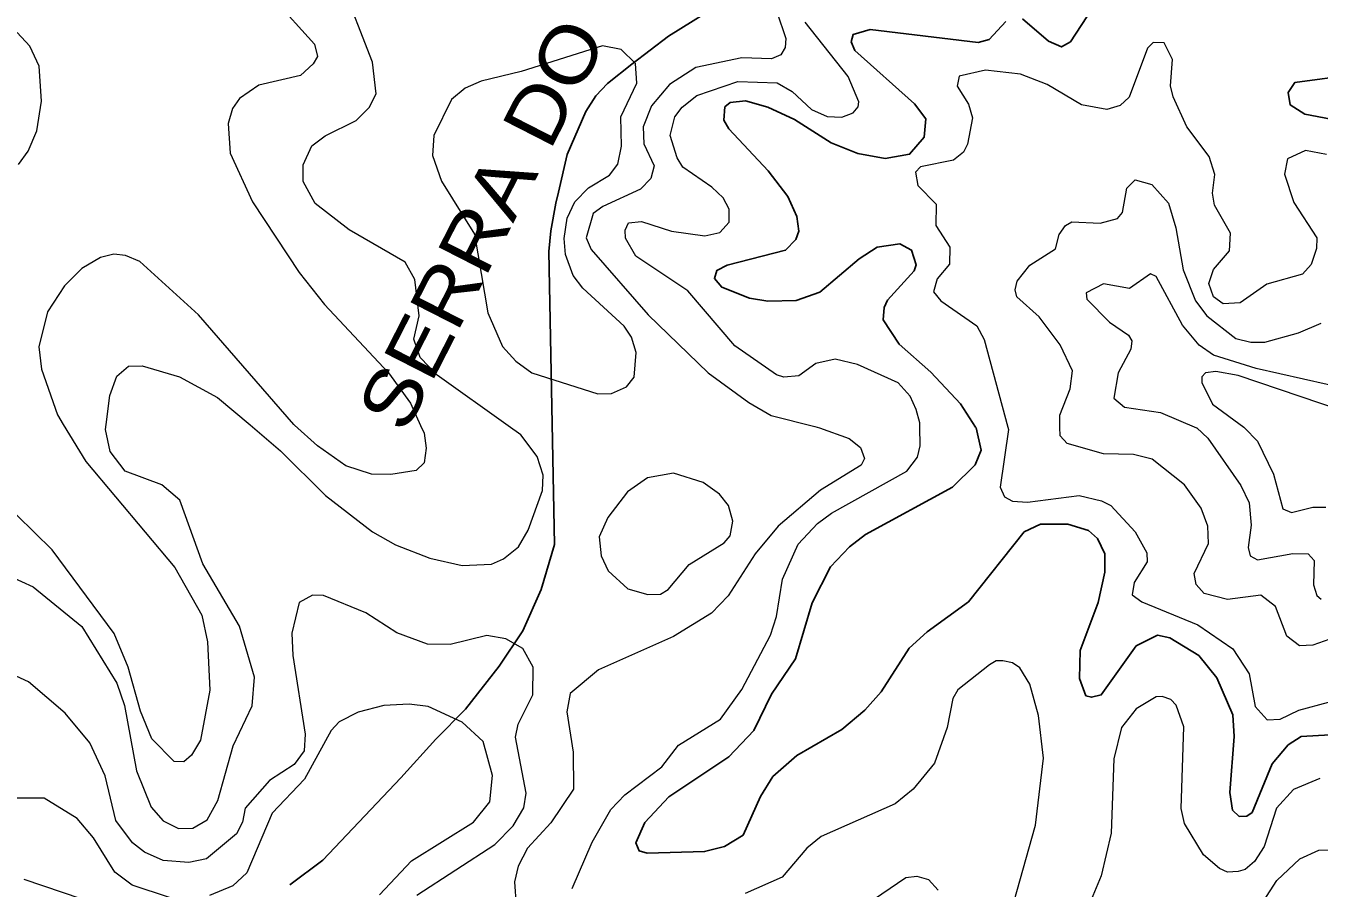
# Model space of a CAD drawing. Extents: x 473.9 to 500, y 7733.1 to 7760.8.
# Drawn here: x 484.875 to 487.667, y 7745.353 to 7747.215 of the extents above; entities that cross this region are included whole.
import ezdxf
from ezdxf.enums import TextEntityAlignment as Align

# ---------------------------------------------------------------- set-up
doc = ezdxf.new("R2010")
doc.units = 0
doc.header["$LTSCALE"] = 0.032
for name, color, linetype, lineweight in [('1', 7, 'Continuous', 25), ('2', 7, 'Continuous', 13), ('26', 7, 'Continuous', 25)]:
    doc.layers.add(name, color=color, linetype=linetype, lineweight=lineweight)

msp = doc.modelspace()

# ---------------------------------------------------------------- linework, layer by layer
at = {"layer": '1'}
for points in [[(487.1661, 7747.234), (487.1303, 7747.1799), (487.1109, 7747.1691), (487.0831, 7747.1814), (487.0268, 7747.2295)], [(486.991, 7747.2242), (486.9546, 7747.1848), (486.9312, 7747.179), (486.6977, 7747.2069), (486.661, 7747.1958), (486.657, 7747.1798), (486.6648, 7747.1611), (486.7936, 7747.0462), (486.8182, 7747.014), (486.8145, 7746.9742), (486.7831, 7746.9375), (486.7301, 7746.9282), (486.6714, 7746.9387), (486.6138, 7746.9622), (486.5345, 7747.0122), (486.4767, 7747.0388), (486.4287, 7747.0528)], [(487.8745, 7746.9789), (487.6368, 7747.0239), (487.6051, 7747.0438), (487.6004, 7747.0708), (487.6149, 7747.092), (487.7438, 7747.1092)], [(486.4287, 7747.0528), (486.3952, 7747.0489), (486.3838, 7747.0395), (486.3817, 7747.0111), (486.3925, 7746.9924), (486.4773, 7746.9014), (486.5202, 7746.8461), (486.5395, 7746.8026), (486.5436, 7746.7712), (486.5371, 7746.7534), (486.5152, 7746.7302), (486.3889, 7746.6978), (486.3668, 7746.6866), (486.3615, 7746.6689), (486.3773, 7746.6506), (486.437, 7746.6268), (486.4768, 7746.6205), (486.5379, 7746.6217), (486.5895, 7746.6395), (486.6744, 7746.7119), (486.7133, 7746.7366), (486.7618, 7746.7439), (486.7871, 7746.7305), (486.7974, 7746.6988), (486.7931, 7746.6857), (486.7353, 7746.6222), (486.7279, 7746.6067), (486.726, 7746.5795), (486.7605, 7746.5273), (486.8287, 7746.467), (486.893, 7746.3987), (486.9256, 7746.3483), (486.9268, 7746.3464), (486.9375, 7746.2981), (486.9248, 7746.2668), (486.876, 7746.2186), (486.6878, 7746.1165), (486.6535, 7746.0899), (486.6124, 7746.0465), (486.5725, 7745.9685), (486.5363, 7745.8476), (486.4848, 7745.7715), (486.4467, 7745.6934), (486.3929, 7745.6364), (486.2634, 7745.5496), (486.2111, 7745.4942), (486.1915, 7745.4508), (486.1993, 7745.433), (486.2161, 7745.428), (486.3404, 7745.4318), (486.3831, 7745.4428), (486.4236, 7745.4674), (486.4611, 7745.5506), (486.4875, 7745.5937), (486.5397, 7745.6392), (486.6364, 7745.6954), (486.6863, 7745.7369), (486.7216, 7745.7765), (486.7824, 7745.8706), (486.8208, 7745.9061), (486.9102, 7745.9706), (487.0306, 7746.1221), (487.0657, 7746.1383), (487.1248, 7746.1384), (487.1691, 7746.1247), (487.1888, 7746.1076), (487.2045, 7746.0747), (487.2047, 7746.0353), (487.19, 7745.9698), (487.1516, 7745.8658), (487.15, 7745.8051), (487.1637, 7745.7681), (487.1761, 7745.7648), (487.197, 7745.7698), (487.2724, 7745.8759), (487.3183, 7745.8988), (487.345, 7745.8931), (487.4074, 7745.8551), (487.4468, 7745.8068), (487.481, 7745.7269), (487.4843, 7745.6803), (487.4747, 7745.559), (487.4806, 7745.5213), (487.4947, 7745.5078), (487.511, 7745.5083), (487.5228, 7745.5164), (487.5659, 7745.6213), (487.6008, 7745.6625), (487.6287, 7745.6801), (487.6915, 7745.6838)]]:
    msp.add_lwpolyline(points, dxfattribs=at)
at = {"layer": '2'}
for points in [[(484.8139, 7746.0378), (484.89, 7746.0036), (484.9957, 7745.918), (485.0712, 7745.795), (485.0873, 7745.7468), (485.1133, 7745.6063), (485.1448, 7745.5277), (485.171, 7745.4981), (485.2042, 7745.4813), (485.235, 7745.4826), (485.2659, 7745.5002), (485.289, 7745.5419), (485.3221, 7745.6599), (485.3633, 7745.7463), (485.3682, 7745.8086), (485.3358, 7745.9183), (485.2567, 7746.0529), (485.207, 7746.1905), (485.1682, 7746.2239), (485.0889, 7746.2532), (485.0568, 7746.2956), (485.0465, 7746.3433), (485.0478, 7746.354), (485.0556, 7746.4162), (485.0708, 7746.4584), (485.0965, 7746.4795), (485.1259, 7746.4808), (485.2063, 7746.4567), (485.2882, 7746.4124), (485.3587, 7746.353), (485.4248, 7746.2973), (485.5217, 7746.2004), (485.6234, 7746.122), (485.6731, 7746.0939), (485.7471, 7746.0651), (485.8166, 7746.0493), (485.88, 7746.0521), (485.9059, 7746.0635), (485.9386, 7746.0899), (485.959, 7746.1257), (485.99, 7746.211), (485.992, 7746.2442), (485.9784, 7746.2849), (485.9438, 7746.3316), (485.9159, 7746.3513), (485.7625, 7746.4601), (485.726, 7746.4987), (485.7123, 7746.5379), (485.7237, 7746.5888), (485.7148, 7746.6671), (485.6934, 7746.7047), (485.5728, 7746.7742), (485.4993, 7746.8309), (485.4735, 7746.8782), (485.4737, 7746.9146), (485.492, 7746.9554), (485.5207, 7746.9772), (485.5877, 7747.0104), (485.6157, 7747.0384), (485.631, 7747.0675), (485.6228, 7747.136), (485.555, 7747.3123)], [(485.4092, 7747.2739), (485.4977, 7747.175), (485.5041, 7747.1485), (485.4952, 7747.1324), (485.4679, 7747.1075), (485.3779, 7747.0866), (485.336, 7747.0576), (485.3208, 7747.0359), (485.3111, 7747.0038), (485.3159, 7746.9394), (485.3642, 7746.8349), (485.4647, 7746.6821), (485.5194, 7746.613), (485.6577, 7746.4651), (485.7051, 7746.3999), (485.727, 7746.3519), (485.7348, 7746.3348), (485.7389, 7746.3027), (485.7348, 7746.2713), (485.7172, 7746.2544), (485.6625, 7746.2456), (485.6207, 7746.2464), (485.5652, 7746.2649), (485.5041, 7746.3075), (485.4549, 7746.3527), (485.4534, 7746.3541), (485.2476, 7746.5905), (485.1206, 7746.7055), (485.09, 7746.7191), (485.0643, 7746.7215), (485.0354, 7746.7143), (484.9952, 7746.691), (484.9582, 7746.6532), (484.9212, 7746.5969), (484.9027, 7746.5213), (484.9083, 7746.4731), (484.9429, 7746.375), (484.9554, 7746.3542), (485.004, 7746.2737), (485.1961, 7746.0454), (485.2548, 7745.9425), (485.2669, 7745.8846), (485.2717, 7745.78), (485.2516, 7745.6723), (485.2323, 7745.6401), (485.2154, 7745.6257), (485.1945, 7745.6265), (485.1463, 7745.6755), (485.1222, 7745.735), (485.0956, 7745.8299), (485.0651, 7745.9023), (484.9316, 7746.0832), (484.8552, 7746.1579)], [(486.4964, 7747.2445), (486.5154, 7747.187), (486.5145, 7747.1679), (486.5049, 7747.1519), (486.4847, 7747.1434), (486.4209, 7747.1452), (486.3212, 7747.1247), (486.2643, 7747.0876), (486.2259, 7747.0422), (486.2078, 7746.9967), (486.2094, 7746.9597), (486.2316, 7746.912), (486.2245, 7746.8853), (486.202, 7746.8619), (486.1203, 7746.8248), (486.0996, 7746.8095), (486.0846, 7746.7568), (486.0957, 7746.7315), (486.2183, 7746.5908), (486.3479, 7746.4654), (486.4356, 7746.4011), (486.4841, 7746.3734), (486.5785, 7746.3493), (486.5881, 7746.3469), (486.6524, 7746.3236), (486.6771, 7746.3041), (486.6859, 7746.2803), (486.6781, 7746.2659), (486.5903, 7746.2117), (486.4995, 7746.1346), (486.4497, 7746.0747), (486.3912, 7745.9838), (486.355, 7745.9466)], [(484.8585, 7746.9153), (484.8794, 7746.9443), (484.8979, 7746.9877), (484.9083, 7747.052), (484.9035, 7747.1276), (484.8834, 7747.171), (484.856, 7747.1999)], [(486.3234, 7747.064), (486.4118, 7747.0946), (486.4971, 7747.0914), (486.5292, 7747.0729), (486.571, 7747.0343), (486.6048, 7747.019), (486.637, 7747.0174), (486.6611, 7747.0271), (486.6723, 7747.0399), (486.6731, 7747.0504), (486.6506, 7747.1051), (486.5573, 7747.2224)], [(487.6837, 7746.9369), (487.6378, 7746.9456), (487.5991, 7746.9272), (487.5928, 7746.8946), (487.613, 7746.833), (487.6625, 7746.7569), (487.6619, 7746.7336), (487.6504, 7746.6993), (487.6318, 7746.6787), (487.5548, 7746.6566), (487.4967, 7746.6167), (487.4604, 7746.6145), (487.4391, 7746.6292), (487.4289, 7746.6586), (487.4393, 7746.6882), (487.4738, 7746.7287), (487.4761, 7746.7673), (487.4413, 7746.8273), (487.4369, 7746.8536), (487.4425, 7746.8938), (487.4297, 7746.9324), (487.3817, 7746.9962), (487.3519, 7747.061), (487.3468, 7747.0851), (487.3509, 7747.1416), (487.3328, 7747.1776), (487.3089, 7747.1785), (487.2966, 7747.1666), (487.2572, 7747.0605), (487.2377, 7747.0429), (487.2088, 7747.0342), (487.1546, 7747.0437), (487.0802, 7747.0876), (487.0223, 7747.1104), (486.9467, 7747.1186), (486.8903, 7747.1056), (486.8855, 7747.0842), (486.9102, 7747.0455), (486.9192, 7747.016), (486.9083, 7746.9589), (486.8993, 7746.9422), (486.8777, 7746.9246), (486.8067, 7746.9099), (486.7961, 7746.8987), (486.801, 7746.87), (486.8403, 7746.8299), (486.8394, 7746.7838), (486.8699, 7746.7365), (486.869, 7746.7001), (486.8425, 7746.6687), (486.8345, 7746.6406), (486.8508, 7746.6211), (486.9279, 7746.5668), (486.944, 7746.5373), (486.9955, 7746.3481), (486.9969, 7746.3429), (486.9789, 7746.2186), (486.9883, 7746.1975), (487.0053, 7746.1883), (487.0373, 7746.1861), (487.1493, 7746.2004), (487.1976, 7746.1893), (487.2175, 7746.1787), (487.27, 7746.122), (487.2956, 7746.0765), (487.296, 7746.057), (487.2678, 7746.0125), (487.2639, 7745.9862), (487.2844, 7745.9708), (487.4053, 7745.9211)], [(486.054, 7745.3523), (486.0974, 7745.452), (486.1376, 7745.5228), (486.1682, 7745.5541), (486.2478, 7745.6144), (486.284, 7745.6618), (486.3748, 7745.7173), (486.4207, 7745.7816), (486.4826, 7745.899), (486.4954, 7745.9392), (486.5083, 7746.0196), (486.5421, 7746.0952), (486.5839, 7746.1402), (486.6144, 7746.1627), (486.7769, 7746.2528), (486.8002, 7746.2834), (486.8058, 7746.3075), (486.8051, 7746.3487), (486.805, 7746.3573), (486.7969, 7746.3863), (486.7841, 7746.4152), (486.7583, 7746.4441), (486.6707, 7746.4835), (486.6225, 7746.4948), (486.5807, 7746.4852), (486.5437, 7746.4586), (486.5115, 7746.4562), (486.4954, 7746.461), (486.4054, 7746.5237), (486.3041, 7746.6427), (486.1915, 7746.7175), (486.1698, 7746.7561), (486.169, 7746.7738), (486.1762, 7746.7891), (486.2044, 7746.7923), (486.2687, 7746.7714), (486.3411, 7746.7609), (486.3732, 7746.7682), (486.3933, 7746.7907), (486.3933, 7746.8188), (486.3805, 7746.8429), (486.3563, 7746.8663), (486.2936, 7746.9097), (486.2808, 7746.9298), (486.2663, 7746.978), (486.2759, 7747.0182), (486.292, 7747.0391), (486.3234, 7747.064)], [(487.703, 7745.8949), (487.6542, 7745.8772), (487.6253, 7745.876), (487.5977, 7745.8971), (487.5732, 7745.9609), (487.5416, 7745.9854), (487.4699, 7745.9762), (487.4193, 7745.9891), (487.4018, 7746.0081), (487.3975, 7746.0319), (487.4284, 7746.0968), (487.4271, 7746.1343), (487.413, 7746.1734), (487.3769, 7746.2233), (487.3069, 7746.2788), (487.2667, 7746.289), (487.2019, 7746.2906), (487.1236, 7746.3127), (487.1079, 7746.3297), (487.1077, 7746.3478), (487.1073, 7746.3739), (487.13, 7746.4307), (487.1345, 7746.4697), (487.1082, 7746.5255), (487.0626, 7746.5861), (487.0147, 7746.6295), (487.0108, 7746.6447), (487.0154, 7746.6635), (487.0429, 7746.6977), (487.0983, 7746.733), (487.1059, 7746.7644), (487.1198, 7746.7838), (487.1333, 7746.7914), (487.1945, 7746.7886), (487.2317, 7746.7987), (487.243, 7746.8117), (487.252, 7746.8638), (487.2705, 7746.882), (487.3058, 7746.872), (487.3419, 7746.8317), (487.3582, 7746.7787), (487.3735, 7746.688), (487.4003, 7746.6209), (487.425, 7746.5886), (487.4877, 7746.5398), (487.52, 7746.5314), (487.55, 7746.5314), (487.6227, 7746.5517), (487.6717, 7746.5729)], [(487.7356, 7746.429), (487.5315, 7746.4749), (487.4394, 7746.5037), (487.4083, 7746.525), (487.3723, 7746.5684), (487.3152, 7746.6737), (487.3031, 7746.6789), (487.2582, 7746.6476), (487.2015, 7746.6579), (487.1645, 7746.6382), (487.166, 7746.6247), (487.2147, 7746.5751), (487.2561, 7746.547), (487.2627, 7746.5346), (487.2611, 7746.5162), (487.2336, 7746.4656), (487.2239, 7746.4108), (487.2474, 7746.3916), (487.3246, 7746.3795), (487.4029, 7746.347), (487.4031, 7746.3469), (487.4272, 7746.3245), (487.4985, 7746.2223), (487.5165, 7746.1847), (487.5205, 7746.1364), (487.5141, 7746.0882), (487.5187, 7746.0701), (487.5343, 7746.0618), (487.6103, 7746.0751), (487.6437, 7746.0749), (487.6568, 7746.0605), (487.6556, 7746.0078), (487.6627, 7745.9845), (487.6719, 7745.9769)], [(487.7604, 7746.3689), (487.4923, 7746.4593), (487.4441, 7746.4682), (487.4219, 7746.4657), (487.4138, 7746.4566), (487.4141, 7746.4446), (487.4373, 7746.3975), (487.5051, 7746.348), (487.5065, 7746.3465), (487.5341, 7746.3182), (487.5687, 7746.2463), (487.589, 7746.1716), (487.6077, 7746.1635), (487.6535, 7746.1756), (487.6822, 7746.1752)], [(485.938, 7745.7065), (485.9695, 7745.7705), (485.9703, 7745.8298), (485.9478, 7745.87), (485.9111, 7745.8911), (485.8698, 7745.898), (485.7905, 7745.8788), (485.7418, 7745.8799), (485.6757, 7745.9043), (485.6088, 7745.9475), (485.5171, 7745.9847), (485.4935, 7745.9852), (485.4651, 7745.9692), (485.4486, 7745.9033), (485.4508, 7745.855), (485.4777, 7745.6851), (485.4755, 7745.6492), (485.4542, 7745.6196), (485.4004, 7745.5854), (485.3483, 7745.5252), (485.3424, 7745.4954), (485.3296, 7745.4703), (485.2647, 7745.4157), (485.2266, 7745.4078), (485.1714, 7745.4123), (485.1311, 7745.4305), (485.1048, 7745.4508), (485.0688, 7745.4991), (485.0457, 7745.595), (485.0126, 7745.6665), (484.9592, 7745.7305), (484.8801, 7745.7984), (484.8439, 7745.8147)], [(486.355, 7745.9466), (486.2728, 7745.8963), (486.1115, 7745.8244), (486.0502, 7745.7727), (486.0427, 7745.7336), (486.0563, 7745.6465), (486.0571, 7745.5662), (486.0081, 7745.4938), (485.9578, 7745.4389), (485.938, 7745.3999), (485.93, 7745.3663), (485.9476, 7745.1072)], [(487.4053, 7745.9211), (487.4814, 7745.8696), (487.5165, 7745.8154), (487.5291, 7745.7452), (487.5549, 7745.7163), (487.5835, 7745.7179), (487.6237, 7745.7368), (487.6878, 7745.7545)], [(486.9819, 7745.2301), (487.055, 7745.489), (487.0719, 7745.6337), (487.0615, 7745.7254), (487.043, 7745.7929), (487.0213, 7745.8283), (487.0052, 7745.8395), (486.9843, 7745.8435), (486.9698, 7745.8435), (486.9553, 7745.8347), (486.887, 7745.7808), (486.8765, 7745.7623), (486.8645, 7745.6996), (486.8371, 7745.6225), (486.7905, 7745.5662), (486.7519, 7745.5348), (486.5919, 7745.4641), (486.5614, 7745.4391), (486.5075, 7745.3764), (486.4279, 7745.341)], [(485.6381, 7745.3385), (485.7075, 7745.4117), (485.8413, 7745.4949), (485.8763, 7745.5393), (485.882, 7745.596), (485.8622, 7745.6695), (485.8167, 7745.7108), (485.7433, 7745.7449), (485.7021, 7745.7503), (485.6474, 7745.7469), (485.5922, 7745.7327), (485.551, 7745.712), (485.5338, 7745.6932), (485.476, 7745.5879), (485.4068, 7745.5146), (485.3518, 7745.3856), (485.3214, 7745.358), (485.2711, 7745.3368)], [(487.4924, 7745.3885), (487.4699, 7745.3869), (487.4522, 7745.3949), (487.4176, 7745.4247), (487.3766, 7745.4922), (487.3694, 7745.5244), (487.375, 7745.7012), (487.3589, 7745.7479), (487.3469, 7745.7599), (487.3284, 7745.7664), (487.3155, 7745.7656), (487.2721, 7745.7398), (487.2408, 7745.6996), (487.2239, 7745.6321), (487.2182, 7745.4713), (487.1965, 7745.3796), (487.1604, 7745.2928)], [(485.7187, 7745.3377), (485.8871, 7745.4468), (485.9266, 7745.4872), (485.9496, 7745.5265), (485.955, 7745.558), (485.9318, 7745.6786), (485.938, 7745.7065)], [(487.6693, 7745.5895), (487.6122, 7745.5654), (487.5752, 7745.5252), (487.5487, 7745.4424), (487.5278, 7745.4102), (487.5077, 7745.3933), (487.4924, 7745.3885)], [(485.1844, 7745.3328), (485.1039, 7745.3591), (485.0665, 7745.3874), (485.0203, 7745.4617), (484.9854, 7745.5034), (484.9142, 7745.5469), (484.7863, 7745.5471)], [(487.5249, 7745.29), (487.5763, 7745.3692), (487.6256, 7745.4158), (487.6671, 7745.4348), (487.6977, 7745.4358)], [(484.8703, 7745.3721), (485.0359, 7745.3157)], [(486.6894, 7745.3172), (486.7746, 7745.3761), (486.7988, 7745.3787), (486.824, 7745.3711), (486.8447, 7745.3487)]]:
    msp.add_lwpolyline(points, dxfattribs=at)
for points in [[(486.1923, 7746.5095), (486.1826, 7746.5421), (486.1664, 7746.5663), (486.0774, 7746.6483), (486.0567, 7746.6752), (486.0402, 7746.7209), (486.037, 7746.7558), (486.0436, 7746.7994), (486.0598, 7746.8345), (486.0899, 7746.8648), (486.1347, 7746.8924), (486.1529, 7746.9157), (486.1609, 7746.9549), (486.1595, 7747.0181), (486.1942, 7747.0906), (486.1912, 7747.1336), (486.1601, 7747.1635), (486.1197, 7747.1718), (485.9444, 7747.116), (485.8575, 7747.0955), (485.8234, 7747.0798), (485.7935, 7747.0559), (485.7553, 7746.9778), (485.7525, 7746.9345), (485.772, 7746.8792), (485.8431, 7746.7647), (485.872, 7746.5947), (485.9038, 7746.5222), (485.933, 7746.4903), (485.9675, 7746.4653), (486.1098, 7746.4198), (486.1395, 7746.4206), (486.1716, 7746.435), (486.1879, 7746.4563)], [(486.3828, 7746.0984), (486.3953, 7746.1136), (486.4013, 7746.1449), (486.3916, 7746.1787), (486.3727, 7746.2033), (486.3373, 7746.2288), (486.2729, 7746.2488), (486.2167, 7746.2387), (486.1738, 7746.2084), (486.1313, 7746.1529), (486.1127, 7746.1112), (486.1171, 7746.0706), (486.1323, 7746.0381), (486.1748, 7745.999), (486.2176, 7745.9868), (486.2452, 7745.9875), (486.2617, 7745.9977), (486.3073, 7746.0517)]]:
    msp.add_lwpolyline(points, close=True, dxfattribs=at)
at = {"layer": '26'}
msp.add_lwpolyline([(485.4448, 7745.3597), (485.5159, 7745.4135), (485.6845, 7745.5912), (485.7602, 7745.6742), (485.824, 7745.7389), (485.8969, 7745.8319), (485.948, 7745.9085), (485.9872, 7745.9978), (486.0163, 7746.0944), (486.0036, 7746.7271), (486.0081, 7746.7717), (486.0191, 7746.8319), (486.0247, 7746.8558), (486.0437, 7746.9367), (486.0838, 7747.0297), (486.1057, 7747.0634), (486.1303, 7747.0899), (486.1832, 7747.1318), (486.2625, 7747.192), (486.3901, 7747.2722)], dxfattribs=at)

# ---------------------------------------------------------------- texts
at = {"layer": '26', "width": 1.15}
msp.add_text('SERRA DO RETIRO', height=0.12, rotation=62.952, dxfattribs=at).set_placement((486.0828, 7747.093), align=Align.CENTER)

doc.saveas('drawing.dxf')
